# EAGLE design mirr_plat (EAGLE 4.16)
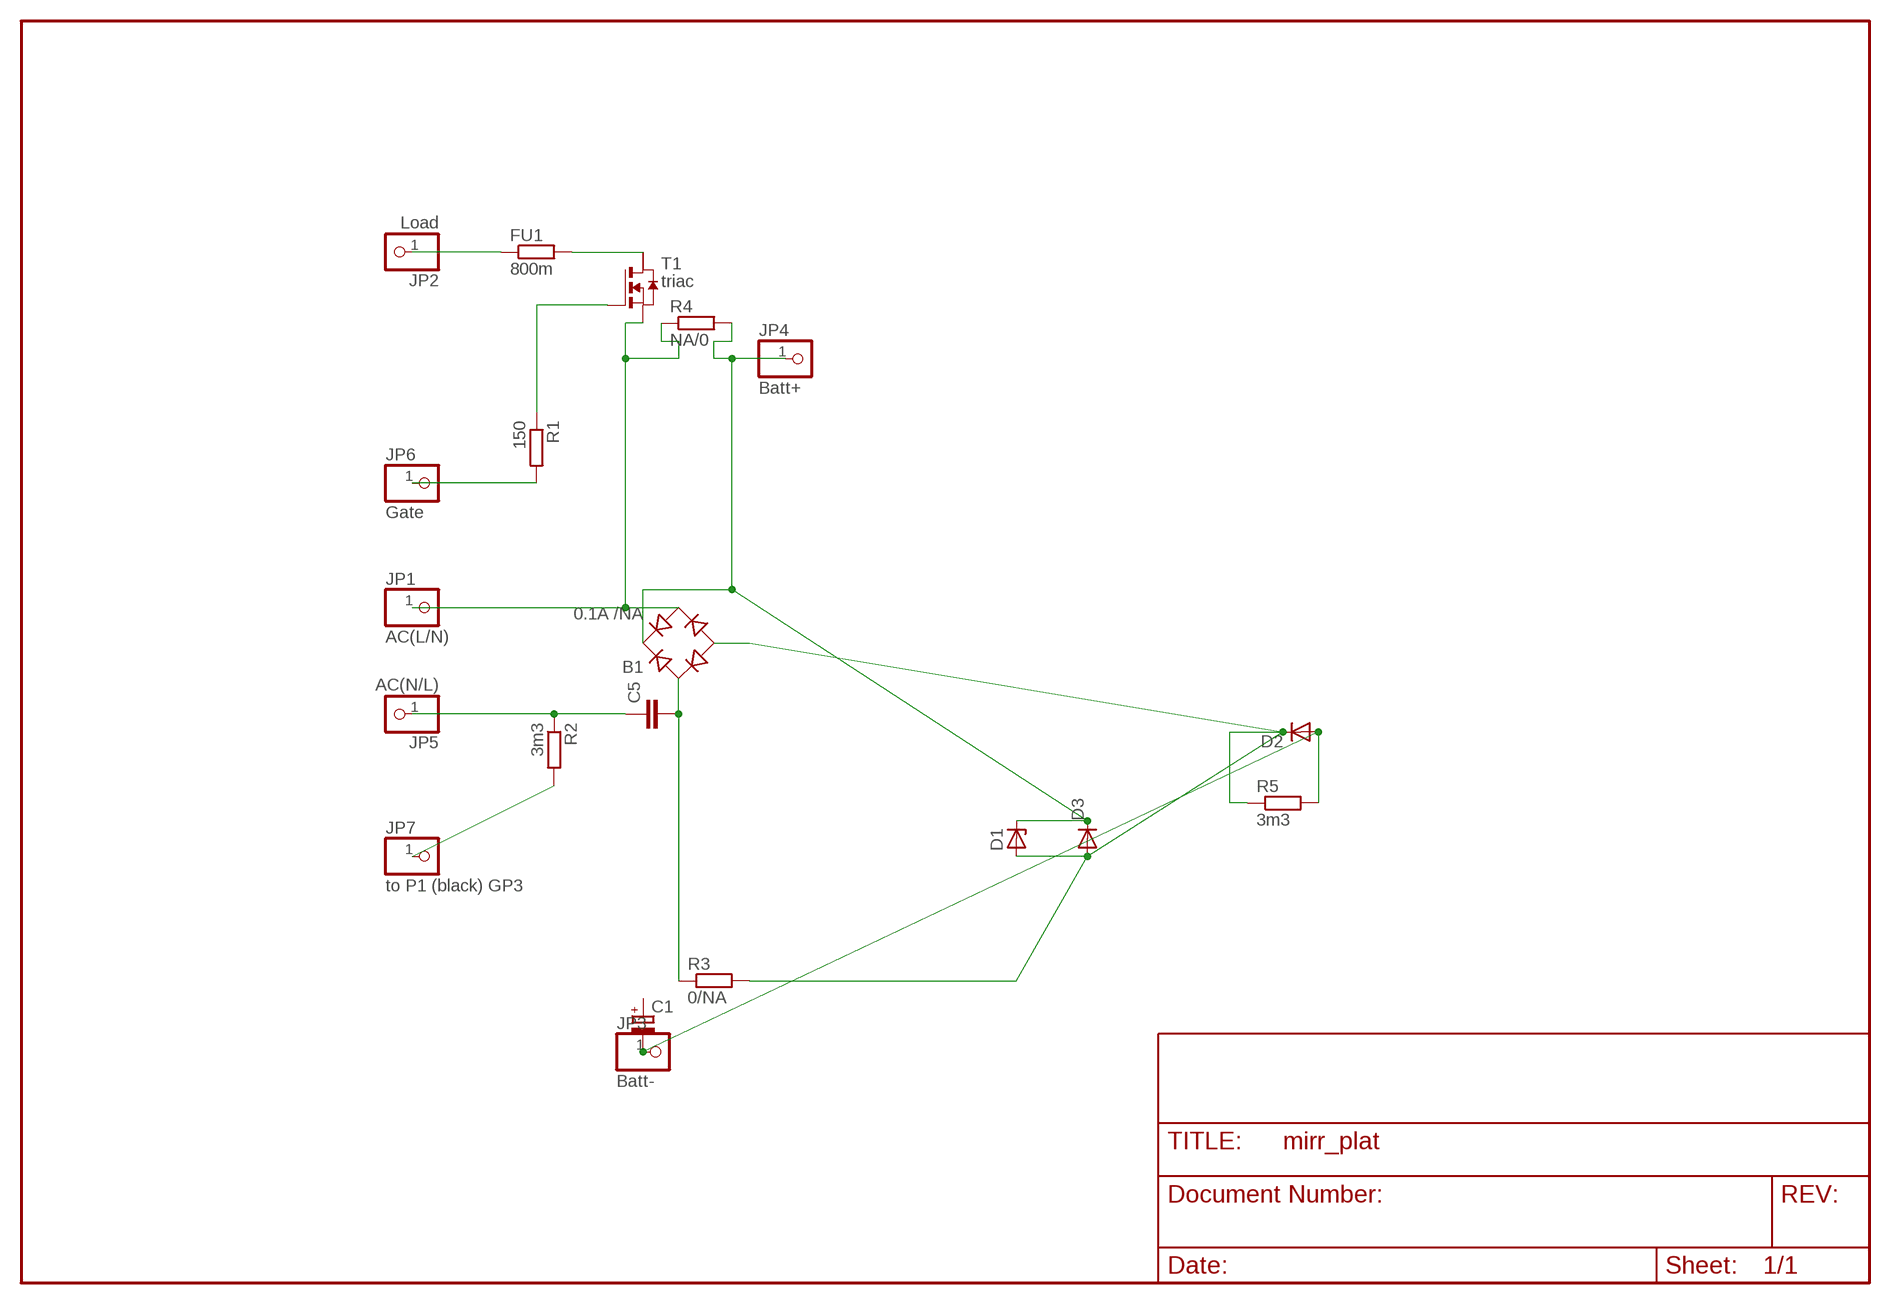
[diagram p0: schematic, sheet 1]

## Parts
B1  0.1A /NA  RECTIFIER-B40S  [B40S]
C1  CPOL-EUE2,5-6E  [E2,5-6E]
C5  C-EU050-025X075  [C050-025X075]
D1  ZENER-DIODESOT23  [SOT23]
D2  DIODE-MELF-MLL41  [MELF-MLL41]
D3  DIODE-MINIMELF  [MINIMELF]
FU1  800m  R-EU_0204/5  [0204/5]
JP1  AC(L/N)  PINHD-1X1  [1X01]
JP2  Load  PINHD-1X1  [1X01]
JP3  Batt-  PINHD-1X1  [1X01]
JP4  Batt+  PINHD-1X1  [1X01]
JP5  AC(N/L)  PINHD-1X1  [1X01]
JP6  Gate  PINHD-1X1  [1X01]
JP7  to P1 (black) GP3  PINHD-1X1  [1X01]
R1  150  R-EU_R1206  [R1206]
R2  3m3  R-EU_R1206  [R1206]
R3  0/NA  R-EU_R1206  [R1206]
R4  NA/0  R-EU_R1206  [R1206]
R5  3m3  R-EU_R1206  [R1206]
T1  triac  NMOSSOT223  [SOT223]

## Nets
N$1: B1.AC2 JP1.1 R4.1 T1.3(S)
N$2: C1.- D2.A JP3.1 R5.2
N$3: R1.1 T1.1(G)
N$4: FU1.1 JP2.1
N$5: JP7.1 R2.2
N$6: B1.- D1.1(A) D2.C D3.A R3.2 R5.1
N$7: B1.AC1 C5.2 R3.1
N$9: FU1.2 T1.2(D)
N$10: B1.+ D1.3(C) D3.C JP4.1 R4.2
N$11: JP6.1 R1.2
N$37: C5.1 JP5.1 R2.1
Unconnected: C1.+ T1.4(D2)

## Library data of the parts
B1 = rectifier:RECTIFIER-: Rectifier
C1 = rcl(2):CPOL-EU: POLARIZED CAPACITOR, European symbol
C5 = rcl:C-EU: CAPACITOR, European symbol
D1 = diode-1:ZENER-DIODE: Z-Diode
D2 D3 = diode-1:DIODE-: DIODE
FU1 R1-R5 = rcl:R-EU_: RESISTOR, European symbol
JP1-JP7 = pinhead:PINHD-1X1: PIN HEADER
T1 = zetex:NMOSSOT223: MOS FET

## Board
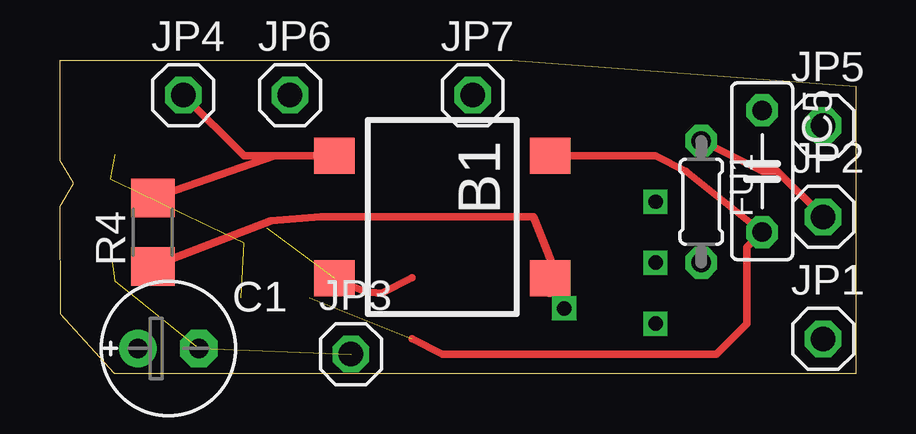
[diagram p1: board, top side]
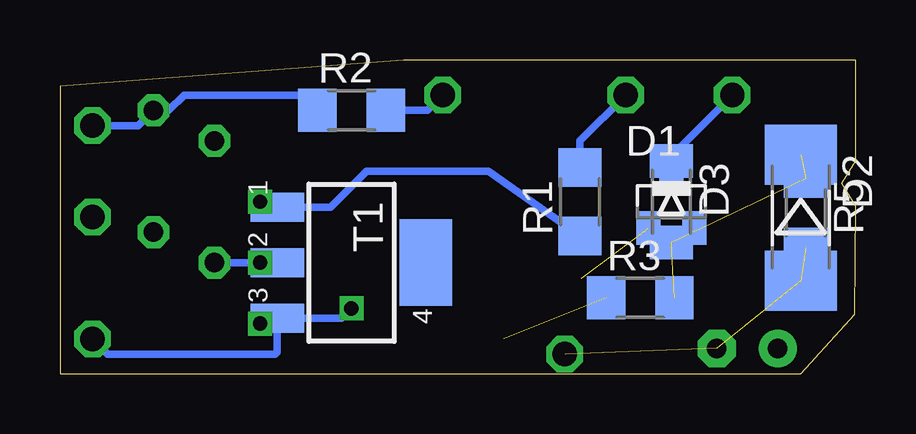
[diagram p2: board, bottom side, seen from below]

Size 33.17 x 13.08 mm. Coordinates in mm from the lower left corner, seen from the top.
Outline: 33.17,0.01 2.29,0 2.29,0.01 0.04,2.48 0,6.99 0.57,7.94 0,8.89 0,13.08 15.18,13.08 18.86,13.08 33.17,12 33.17,0.01
Copper layers (1*16): Top 0.035mm / dielectric 1.5mm / Bottom 0.035mm
Design rules "default": minimum track width 10mil, minimum drill 24mil, track to track 8mil, track to pad 8mil, pad to pad 8mil, via to via 8mil, smd to smd 8mil, copper to edge 40mil, drill to drill 8mil, minimum pad ring 10mil, minimum via ring 8mil, stop-mask expansion 4mil, vias tented up to drill 0mil, thermal gap 10mil

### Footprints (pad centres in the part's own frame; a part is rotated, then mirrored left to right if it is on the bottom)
B40S = smd 1.5 x 1.7: + -2.55,-4.5; - 2.55,-4.5; AC1 -2.55,4.5; AC2 2.55,4.5
E2,5-6E = drill 0.813 pad 1.575 round: + -1.27,0 | drill 0.813 pad 1.575 octagon: - 1.27,0
C050-025X075 = drill 0.813 octagon: 1 -2.54,0; 2 2.54,0
SOT23 = smd 1 x 1.4: 1 -0.95,-1.1; 2 0.95,-1.1; 3 0,1.1
MELF-MLL41 = smd 2.5 x 3: A 2.625,0; C -2.625,0
MINIMELF = smd 1.4 x 1.8: A 1.7,0; C -1.7,0
0204/5 = drill 0.813 octagon: 1 -2.54,0; 2 2.54,0
1X01 = drill 1.016 octagon: 1 0,0
R1206 = smd 1.6 x 1.803: 1 -1.422,0; 2 1.422,0
SOT223 = smd 1.219 x 2.235: 1 -2.311,-3.099; 2 0,-3.099; 3 2.311,-3.099 | smd 3.6 x 2.2: 4 0,3.099

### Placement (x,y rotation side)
B1  15.94,6.54 270 top
C1  4.52,1.06 0 top
C5  29.27,8.45 270 top
D1  7.68,7.18 0 bottom
D2  2.29,6.51 270 bottom
D3  7.68,7.18 270 bottom
FU1  26.73,7.18 270 top
JP1  31.81,1.46 0 top
JP2  31.81,6.54 0 top
JP3  12.13,0.83 0 top
JP4  5.14,11.62 0 top
JP5  31.81,10.35 0 top
JP6  9.59,11.62 0 top
JP7  17.21,11.62 0 top
R1  11.49,7.18 90 bottom
R2  21.02,10.99 0 bottom
R3  8.98,3.17 0 bottom
R4  3.87,5.91 90 top
R5  2.09,6.71 270 bottom
T1  21.02,4.64 270 bottom

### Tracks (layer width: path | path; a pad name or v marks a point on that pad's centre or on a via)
N$1  (via drill 0.6)
  Top 0.305: 21.02,3.37 v21.02,2.73 | R4.1 8.8,6.39 10.86,6.54 19.75,6.54 21.02,3.37 | 21.02,3.37 20.39,3.36 B1.AC2
  Bottom 0.305: JP1.1 31.18,0.83 24.19,0.83 24.12,0.9 T1.3 21.42,2.32 v21.02,2.73
N$2  (3 unrouted)
N$3
  Bottom 0.305: T1.1 21.88,6.95 20.38,8.45 15.3,8.45 R1.1
N$4
  Top 0.305: JP2.1 29.91,8.45 29.27,8.45 FU1.1
N$5
  Bottom 0.305: R2.2 17.84,10.99 JP7.1
N$6  (4 unrouted)
  Top 0.305: B1.- 12.71,3.42 13.4,3.37 14.67,4
  Bottom 0.305: D1.1 8.49,6.08 7.89,5.48 D3.A
N$7  (1 unrouted)
  Top 0.305: B1.AC1 24.82,9.09 26.1,8.45 C5.2 28.64,5.27 28.64,2.1 27.37,0.83 15.94,0.83 14.67,1.46
N$9
  Bottom 0.305: T1.2 FU1.2
N$10
  Top 0.305: 8.95,9.09 7.67,9.09 JP4.1 | 8.95,9.09 B1.+ | R4.2 8.95,9.09
  Bottom 0.305: JP4.1 7.68,9.08 D3.C D1.3 7.68,7.81
N$11
  Bottom 0.305: R1.2 11.49,9.72 JP6.1
N$12  (via drill 0.6)
  other vias: 24.83,2.1
N$13  (via drill 0.6)
  other vias: 24.83,4.64
N$14  (via drill 0.6)
  other vias: 24.83,7.18
N$37
  Bottom 0.305: JP5.1 29.91,10.35 C5.1 28.64,10.99 28,11.62 22.92,11.62 22.29,10.99 R2.1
